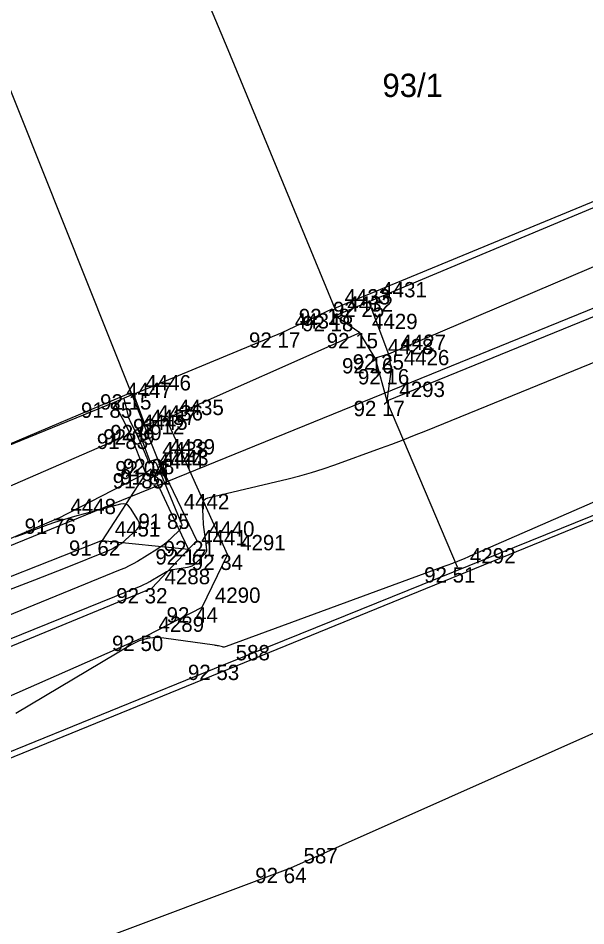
# Model space of a CAD drawing. Extents: x -711081 to -709338, y -1025122 to -1024092.
# Drawn here: x -710004.26 to -709993.89, y -1024617.51 to -1024600.93 of the extents above; entities that cross this region are included whole.
import ezdxf

# ---------------------------------------------------------------- set-up
doc = ezdxf.new("R2010")
doc.units = 0
for name, color, linetype in [('Ex_Major Contours', 7, 'Continuous'), ('Ex_Minor Contours', 7, 'Continuous'), ('Z_betonova_konstrukce', 7, 'Continuous'), ('Z_body', 7, 'Continuous'), ('Z_body_cisla', 7, 'Continuous'), ('Z_body_vysky_redukovane', 7, 'Continuous'), ('Z_budova', 7, 'Continuous'), ('Z_hrany_paty', 7, 'Continuous'), ('Z_katastr_cisla_stavebni', 7, 'Continuous'), ('Z_katastr_hranice', 7, 'Continuous'), ('Z_katastr_vnitrni_kresba', 7, 'Continuous'), ('Z_komunikace', 7, 'Continuous'), ('Z_komunikace_osa', 7, 'Continuous'), ('Z_rozhranni', 7, 'Continuous'), ('Z_vstupy', 7, 'Continuous'), ('Z_zelen_obvod', 7, 'Continuous')]:
    doc.layers.add(name, color=color, linetype=linetype)

# ---------------------------------------------------------------- blocks, each defined once
blk = doc.blocks.new('POINT_DISPLAY')
blk.add_line((0, 0), (0, 0))

msp = doc.modelspace()

# ---------------------------------------------------------------- linework, layer by layer
at = {"layer": 'Ex_Major Contours'}
msp.add_lwpolyline([(-710002.335, -1024607.875), (-710002.256, -1024608.198), (-710002.248, -1024608.227), (-710002.238, -1024608.255), (-710002.226, -1024608.282), (-710002.213, -1024608.309), (-710002.157, -1024608.415), (-710002.143, -1024608.441), (-710002.13, -1024608.468), (-710002.117, -1024608.495), (-710002.104, -1024608.523), (-710001.944, -1024608.89), (-710001.936, -1024608.907), (-710001.929, -1024608.925), (-710001.922, -1024608.942), (-710001.915, -1024608.96), (-710001.877, -1024609.06), (-710001.876, -1024609.062), (-710001.874, -1024609.063), (-710001.872, -1024609.063), (-710001.87, -1024609.061), (-710001.861, -1024609.051), (-710001.859, -1024609.049), (-710001.856, -1024609.047), (-710001.853, -1024609.046), (-710001.85, -1024609.045), (-710001.781, -1024609.039), (-710001.769, -1024609.039), (-710001.759, -1024609.043), (-710001.751, -1024609.05), (-710001.745, -1024609.06), (-710001.661, -1024609.255), (-710001.645, -1024609.291), (-710001.63, -1024609.328), (-710001.614, -1024609.364), (-710001.599, -1024609.401), (-710001.279, -1024610.164), (-710001.275, -1024610.176), (-710001.274, -1024610.188), (-710001.275, -1024610.2), (-710001.28, -1024610.212), (-710001.303, -1024610.261), (-710001.309, -1024610.272), (-710001.317, -1024610.283), (-710001.325, -1024610.293), (-710001.334, -1024610.303), (-710001.557, -1024610.507), (-710001.599, -1024610.542), (-710001.642, -1024610.576), (-710001.686, -1024610.608), (-710001.732, -1024610.637), (-710002.087, -1024610.852), (-710002.162, -1024610.896), (-710002.239, -1024610.936), (-710002.318, -1024610.974), (-710002.398, -1024611.008), (-710004.76, -1024611.966)], dxfattribs=at)
at = {"layer": 'Ex_Minor Contours'}
for points in [[(-710007.12, -1024613.366), (-710002.02, -1024611.297), (-710001.966, -1024611.274), (-710001.913, -1024611.249), (-710001.861, -1024611.221), (-710001.81, -1024611.192), (-710001.601, -1024611.065), (-710001.553, -1024611.039), (-710001.504, -1024611.019), (-710001.452, -1024611.003), (-710001.399, -1024610.993), (-710001.168, -1024610.958), (-710001.124, -1024610.948), (-710001.083, -1024610.931), (-710001.045, -1024610.907), (-710001.011, -1024610.877), (-710000.837, -1024610.699), (-710000.828, -1024610.687), (-710000.822, -1024610.675), (-710000.819, -1024610.662), (-710000.819, -1024610.647), (-710000.825, -1024610.587), (-710000.826, -1024610.572), (-710000.828, -1024610.557), (-710000.83, -1024610.542), (-710000.832, -1024610.527), (-710000.87, -1024610.226), (-710000.876, -1024610.175), (-710000.881, -1024610.124), (-710000.884, -1024610.073), (-710000.887, -1024610.022), (-710000.894, -1024609.818), (-710000.89, -1024609.771), (-710000.872, -1024609.735), (-710000.842, -1024609.709), (-710000.799, -1024609.692), (-709999.332, -1024609.345), (-709999.117, -1024609.291), (-709998.903, -1024609.23), (-709998.691, -1024609.163), (-709998.481, -1024609.091), (-709997.645, -1024608.787), (-709997.436, -1024608.71), (-709997.228, -1024608.631), (-709997.021, -1024608.55), (-709996.814, -1024608.467), (-709992.068, -1024606.532)], [(-709989.029, -1024607.716), (-709996.01, -1024610.76), (-709996.036, -1024610.771), (-709996.063, -1024610.783), (-709996.09, -1024610.794), (-709996.117, -1024610.805), (-709996.226, -1024610.85), (-709996.252, -1024610.86), (-709996.278, -1024610.87), (-709996.304, -1024610.88), (-709996.33, -1024610.89), (-709996.435, -1024610.928), (-709996.487, -1024610.947), (-709996.539, -1024610.966), (-710000.465, -1024612.41), (-710000.482, -1024612.415), (-710000.499, -1024612.417), (-710000.517, -1024612.417), (-710000.534, -1024612.414), (-710000.605, -1024612.398), (-710000.622, -1024612.394), (-710000.64, -1024612.391), (-710000.658, -1024612.388), (-710000.676, -1024612.385), (-710001.6, -1024612.255), (-710001.757, -1024612.246), (-710001.909, -1024612.263), (-710002.056, -1024612.306), (-710002.198, -1024612.375), (-710004.305, -1024613.63)], [(-710008.785, -1024613.041), (-710003.957, -1024611.192), (-710003.817, -1024611.137), (-710003.677, -1024611.083), (-710003.537, -1024611.027), (-710003.397, -1024610.971), (-710002.616, -1024610.654), (-710002.589, -1024610.642), (-710002.562, -1024610.629), (-710002.536, -1024610.616), (-710002.51, -1024610.601), (-710002.408, -1024610.539), (-710002.383, -1024610.523), (-710002.358, -1024610.505), (-710002.335, -1024610.487), (-710002.312, -1024610.468), (-710002.098, -1024610.272), (-710002.065, -1024610.231), (-710002.049, -1024610.188), (-710002.053, -1024610.143), (-710002.075, -1024610.095), (-710002.211, -1024609.879), (-710002.248, -1024609.836), (-710002.291, -1024609.809), (-710002.341, -1024609.799), (-710002.397, -1024609.807), (-710003.235, -1024610.032), (-710003.358, -1024610.067), (-710003.48, -1024610.104), (-710003.602, -1024610.144), (-710003.722, -1024610.187), (-710004.203, -1024610.365), (-710004.324, -1024610.408)]]:
    msp.add_lwpolyline(points, dxfattribs=at)
at = {"layer": 'Z_betonova_konstrukce'}
for p, q in [((-710002.16, -1024607.8), (-710001.95, -1024608.36)), ((-710002.51, -1024607.95), (-710002.22, -1024608.52)), ((-710001.95, -1024608.36), (-710002.08, -1024608.44)), ((-710002.08, -1024608.44), (-710001.86, -1024609.02)), ((-710001.93, -1024609.24), (-710002.22, -1024608.52)), ((-710001.86, -1024609.02), (-710001.72, -1024608.98)), ((-710001.72, -1024608.98), (-710001, -1024610.48)), ((-710001.84, -1024609.17), (-710001.93, -1024609.24)), ((-710001.46, -1024609.98), (-710001.84, -1024609.17)), ((-710001.15, -1024610.63), (-710001.46, -1024609.98)), ((-710001, -1024610.48), (-710001.15, -1024610.63))]:
    msp.add_line(p, q, dxfattribs=at)
at = {"layer": 'Z_budova'}
for p, q in [((-709991.06, -1024603.27), (-709997.86, -1024606.11)), ((-709997.86, -1024606.11), (-709998.47, -1024606.37)), ((-709998.47, -1024606.37), (-709998.53, -1024606.24)), ((-710002.16, -1024607.8), (-710002.51, -1024607.95)), ((-710002.51, -1024607.95), (-710007.42, -1024609.95))]:
    msp.add_line(p, q, dxfattribs=at)
at = {"layer": 'Z_hrany_paty'}
for p, q in [((-710001.93, -1024609.24), (-710002.73, -1024610.47)), ((-710002.73, -1024610.47), (-710008.95, -1024612.93)), ((-710002.73, -1024610.47), (-710001.15, -1024610.63)), ((-710001.82, -1024611.34), (-710001.15, -1024610.63)), ((-710007.97, -1024613.87), (-710001.82, -1024611.34))]:
    msp.add_line(p, q, dxfattribs=at)
at = {"layer": 'Z_katastr_hranice'}
for p, q in [((-710002.2, -1024607.77), (-710006.32, -1024597.48)), ((-709990.35, -1024604.84), (-710001.55, -1024609.4)), ((-710001.55, -1024609.4), (-710002.2, -1024607.77)), ((-710023.32, -1024618.27), (-710001.55, -1024609.4))]:
    msp.add_line(p, q, dxfattribs=at)
at = {"layer": 'Z_katastr_vnitrni_kresba'}
for p, q in [((-709940.71, -1024588.46), (-710021.21, -1024621.3)), ((-710000.43, -1024601.51), (-710001.58, -1024598.73)), ((-709998.48, -1024606.23), (-710000.43, -1024601.51)), ((-709998.48, -1024606.23), (-709991.04, -1024603.15)), ((-710007.41, -1024609.97), (-710002.2, -1024607.77))]:
    msp.add_line(p, q, dxfattribs=at)
at = {"layer": 'Z_komunikace'}
for p, q in [((-710000.51, -1024612.74), (-709985.58, -1024606.7)), ((-710013.92, -1024618.19), (-710000.51, -1024612.74))]:
    msp.add_line(p, q, dxfattribs=at)
at = {"layer": 'Z_komunikace_osa'}
for p, q in [((-709999.28, -1024616.45), (-709984.54, -1024609.89)), ((-710012.73, -1024621.49), (-709999.28, -1024616.45))]:
    msp.add_line(p, q, dxfattribs=at)
at = {"layer": 'Z_rozhranni'}
for p, q in [((-709990.41, -1024604.05), (-709997.5, -1024607.07)), ((-709997.53, -1024607.92), (-709990.22, -1024604.94)), ((-709997.86, -1024606.11), (-709997.5, -1024607.07)), ((-709998.02, -1024606.68), (-709998.47, -1024606.37)), ((-709998.02, -1024606.68), (-710001.56, -1024608.25)), ((-709997.74, -1024607.14), (-709998.02, -1024606.68)), ((-709997.5, -1024607.07), (-709997.74, -1024607.14)), ((-709997.74, -1024607.14), (-709997.53, -1024607.92)), ((-709996.24, -1024610.96), (-709997.53, -1024607.92)), ((-710001.95, -1024608.36), (-710001.56, -1024608.25)), ((-710001.56, -1024608.25), (-710000.44, -1024610.73)), ((-710005.73, -1024610.05), (-710002.22, -1024608.52)), ((-710000.9, -1024611.69), (-710000.44, -1024610.73)), ((-710001.92, -1024612.21), (-710000.9, -1024611.69)), ((-710007.82, -1024614.81), (-710001.92, -1024612.21))]:
    msp.add_line(p, q, dxfattribs=at)
at = {"layer": 'Z_vstupy'}
for p, q in [((-709999.44, -1024606.67), (-709998.53, -1024606.24)), ((-710002.16, -1024607.8), (-709999.44, -1024606.67))]:
    msp.add_line(p, q, dxfattribs=at)
at = {"layer": 'Z_zelen_obvod'}
for p, q in [((-709997.5, -1024607.07), (-709997.45, -1024607.34)), ((-709997.45, -1024607.34), (-709997.53, -1024607.92)), ((-710003.54, -1024610.07), (-710001.93, -1024609.24)), ((-710003.54, -1024610.07), (-710006.25, -1024611.22))]:
    msp.add_line(p, q, dxfattribs=at)

# ---------------------------------------------------------------- block references
at = {"layer": 'Z_body'}
for p in [(-709997.86, -1024606.11), (-709998.53, -1024606.24), (-709998.47, -1024606.37), (-709999.44, -1024606.67), (-709998.02, -1024606.68), (-709997.74, -1024607.14), (-709997.5, -1024607.07), (-709997.45, -1024607.34), (-710002.16, -1024607.8), (-710002.51, -1024607.95), (-709997.53, -1024607.92), (-710001.56, -1024608.25), (-710002.08, -1024608.44), (-710001.95, -1024608.36), (-710002.22, -1024608.52), (-710001.72, -1024608.98), (-710001.86, -1024609.02), (-710001.84, -1024609.17), (-710001.93, -1024609.24), (-710001.46, -1024609.98), (-710003.54, -1024610.07), (-710002.73, -1024610.47), (-710001, -1024610.48), (-710001.15, -1024610.63), (-710000.44, -1024610.73), (-709996.24, -1024610.96), (-710001.82, -1024611.34), (-710000.9, -1024611.69), (-710001.92, -1024612.21), (-710000.51, -1024612.74), (-709999.28, -1024616.45)]:
    msp.add_blockref('POINT_DISPLAY', p, dxfattribs=at)

# ---------------------------------------------------------------- texts
at = {"layer": 'Z_body_cisla'}
for s, p in [('4431', (-709997.63, -1024606.03)), ('4433', (-709998.3, -1024606.16)), ('4432', (-709998.25, -1024606.29)), ('4434', (-709999.21, -1024606.6)), ('4429', (-709997.8, -1024606.61)), ('4428', (-709997.51, -1024607.07)), ('4427', (-709997.28, -1024606.99)), ('4426', (-709997.22, -1024607.27)), ('4446', (-710001.94, -1024607.73)), ('4447', (-710002.29, -1024607.87)), ('4293', (-709997.3, -1024607.85)), ('4436', (-710001.72, -1024608.28)), ('4435', (-710001.34, -1024608.18)), ('4445', (-710002, -1024608.45)), ('4437', (-710001.85, -1024608.36)), ('4438', (-710001.63, -1024608.95)), ('4439', (-710001.5, -1024608.9)), ('4443', (-710001.62, -1024609.1)), ('4444', (-710001.71, -1024609.16)), ('4442', (-710001.24, -1024609.9)), ('4448', (-710003.31, -1024609.99)), ('4451', (-710002.5, -1024610.4)), ('4440', (-710000.78, -1024610.4)), ('4441', (-710000.92, -1024610.56)), ('4291', (-710000.21, -1024610.65)), ('4292', (-709996.01, -1024610.89)), ('4288', (-710001.59, -1024611.27)), ('4290', (-710000.67, -1024611.61)), ('4289', (-710001.7, -1024612.14)), ('588', (-710000.29, -1024612.66)), ('587', (-709999.05, -1024616.37))]:
    msp.add_text(s, height=0.28, dxfattribs=at).set_placement(p)
at = {"layer": 'Z_body_vysky_redukovane'}
for s, p in [('92 25', (-709998.513, -1024606.39)), ('92 18', (-709999.137, -1024606.52)), ('92 18', (-709999.077, -1024606.65)), ('92 17', (-710000.047, -1024606.95)), ('92 15', (-709998.627, -1024606.96)), ('92 16', (-709998.347, -1024607.42)), ('92 25', (-709998.153, -1024607.35)), ('92 16', (-709998.057, -1024607.62)), ('92 15', (-710002.767, -1024608.08)), ('91 85', (-710003.117, -1024608.23)), ('92 17', (-709998.137, -1024608.2)), ('92 12', (-710002.167, -1024608.53)), ('92 09', (-710002.71, -1024608.72)), ('92 09', (-710002.58, -1024608.64)), ('91 83', (-710002.827, -1024608.8)), ('92 08', (-710002.35, -1024609.26)), ('92 04', (-710002.49, -1024609.3)), ('91 81', (-710002.4, -1024609.45)), ('91 85', (-710002.537, -1024609.52)), ('91 85', (-710002.067, -1024610.26)), ('91 76', (-710004.147, -1024610.35)), ('91 62', (-710003.337, -1024610.75)), ('92 21', (-710001.607, -1024610.76)), ('92 17', (-710001.757, -1024610.91)), ('92 34', (-710001.093, -1024611.01)), ('92 51', (-709996.847, -1024611.24)), ('92 32', (-710002.473, -1024611.62)), ('92 44', (-710001.553, -1024611.97)), ('92 50', (-710002.55, -1024612.49)), ('92 53', (-710001.163, -1024613.02)), ('92 64', (-709999.933, -1024616.73))]:
    msp.add_text(s, height=0.28, dxfattribs=at).set_placement(p)
at = {"layer": 'Z_katastr_cisla_stavebni'}
msp.add_text('93/1', height=0.425, dxfattribs=at).set_placement((-709997.609, -1024602.37))

doc.saveas('drawing.dxf')
